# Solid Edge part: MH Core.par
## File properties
Author: Dan
Template: FH Insert .par
Last saved by: Dan
Revision: 22
Application: Solid Edge
Density: 7833.000 kg/m^3
Accuracy: 0.990
Material: Steel
Face Style: Steel
Fill Style: ANSI32(Steel)
Virtual Style: Machined steel
Coef. of Thermal Exp: 1.3e-05
Thermal Conductivity: 32.0
Specific Heat: 481.0
Modulus of Elasticity: 199947953000.0
Poisson's Ratio: 0.29
Yield Stress: 262000766.0
Ultimate Stress: 358527364.0
Elongation: 0.0
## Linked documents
FH Insert .par
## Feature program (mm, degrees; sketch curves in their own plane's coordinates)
part copy "CopiedPart_1"
sketch for "ExtrudedProtrusion_1" plane through (0, 0, -36) normal (0, 0, -1) x-axis (-1, 0, 0)
  circle centre (0, 0) radius 22
extrude "ExtrudedProtrusion_1" add finite 5 along -normal
sketch for "Hole_1" plane through (0, 0, -36) normal (0, 0, -1) x-axis (-1, 0, 0)
  hole centre (0, 0) bore radius 9
hole "Hole_1" finite  CounterBoreDepth = 2.2 mm
sketch for "unnamed Cutout 1" plane through (0, 0, -15.2481) normal (0, 0, 1) x-axis (1, 0, 0)
extrude "unnamed Cutout 1" cut to key point along -normal
sketch for "Hole_2" plane through (0, 0, -173) normal (0, 0, -1) x-axis (0, 1, 0)
  hole centre (-19, 0) bore radius 1.621
hole "Hole_2" through
sketch for "unnamed Hole 1" plane through (0, 0, -173) normal (0, 0, -1) x-axis (0, 1, 0)
  hole centre (19, 0) bore radius 1.621
hole "unnamed Hole 1" through
pattern "unnamed Pattern 1" of "Hole_2", "unnamed Hole 1"
Other named dimensions: "Face_Move_1": Distance = 137 mm
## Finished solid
Body 1: solid body, 13 faces, 14 edges, 1 vertex.
  Faces by surface: cylinder 7, plane 5, cone 1
  Edges by curve: circle 14
Bounding box of the edges (mm): 44.000 x 44.000 x 179.000, from (-22, -22, -173) to (22, 22, 6).
Cylindrical faces by radius (mm): R1.621 x2, R8.5 x1, R9 x1, R12.5 x1, R16.75 x1, R22 x1
Conical faces (half-angle, radius in mm at the cone's reference point): 59 deg R9 x1
Planar faces by outward normal: +z 3, -z 2
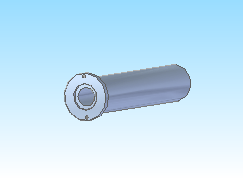
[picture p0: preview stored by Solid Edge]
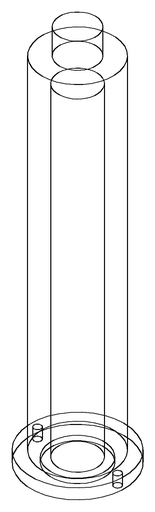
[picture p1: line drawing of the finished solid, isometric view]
